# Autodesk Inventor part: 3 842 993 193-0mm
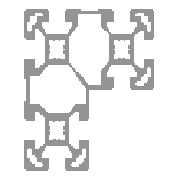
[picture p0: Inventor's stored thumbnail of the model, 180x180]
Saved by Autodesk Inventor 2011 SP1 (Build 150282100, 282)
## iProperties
Category: End -/-
Created: 2011-02
Part Number: 3 842 993 193-0mm
Document SubType Name: Modeling
Designer: SRW
Density: 2.71 g/cm^3
Categories: <MemberInstance><Categories><Category DisplayName="Structural Shapes" InternalName="089c4875-fa83-4c05-b084-43b9cc11f5ed" Mnemonic="GRDR"><CategoryParameter Dis
Stock Number: 3 842 993 193
Description: PROFILE 40x80x80, -/-
Material: Aluminum-6061
Mass: 95.9623 g
Surface Area: 321.468 cm^2
Volume: 35.4105 cm^3
G_L: 25.000 mm
Author: SRW
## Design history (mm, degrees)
node "Blocks"
  sketch "40X80X80"
    geometry: L1 (51.285, 30.766)-(51.552, 30.151); L2 (44.092, 37.611)-(44.706, 37.344); L3 (51.552, 30.151)-(54.492, 30.151); L4 (44.092, 40.551)-(44.092, 37.611); L5 (54.492, 30.151)-(54.492, 33.091); L6 (47.032, 40.551)-(44.092, 40.551); L7 (54.492, 33.091)-(53.878, 33.358); L8 (47.299, 39.937)-(47.032, 40.551); L9 (53.878, 37.344)-(54.492, 37.611); L10 (51.552, 40.551)-(51.285, 39.937); L11 (54.492, 37.611)-(54.492, 40.551); L12 (43.913, 42.851)-(56.085, 42.851); L13 (54.492, 40.551)-(51.552, 40.551); L14 (30.292, 49.351)-(29.292, 49.351); L15 (29.292, 41.151)-(30.792, 41.151); L16 (35.292, 40.351)-(35.292, 45.401); L17 (30.792, 40.351)-(35.292, 40.351); L18 (30.792, 41.151)-(30.792, 40.351); L19 (29.292, 49.351)-(29.292, 41.151); L20 (39.242, 23.887)-(43.206, 27.851); L21 (39.242, 21.351)-(39.242, 23.887); L22 (44.292, 21.351)-(39.242, 21.351); L23 (44.292, 16.783)-(44.292, 21.351); L24 (43.492, 16.783)-(44.292, 16.783); L25 (43.492, 15.283)-(43.492, 16.783); L26 (32.292, 15.283)-(43.492, 15.283); L27 (29.292, 29.551)-(29.292, 18.283); L28 (30.792, 29.551)-(29.292, 29.551); L29 (30.792, 30.351)-(30.792, 29.551); L30 (35.292, 30.351)-(30.792, 30.351); L31 (35.292, 25.301)-(35.292, 30.351); L32 (37.828, 25.301)-(35.292, 25.301); L33 (41.792, 29.265)-(37.828, 25.301); L34 (34.792, 23.601)-(33.792, 23.601); L35 (37.542, 19.851)-(37.542, 20.851); L36 (39.792, 19.851)-(37.542, 19.851); L37 (34.792, 16.851)-(39.792, 16.851); L38 (34.792, 18.101)-(34.792, 16.851); L39 (30.792, 20.851)-(32.042, 20.851); L40 (30.792, 25.851)-(30.792, 20.851); L41 (33.792, 23.601)-(33.792, 25.851); L42 (60.756, 25.301)-(56.792, 29.265); L43 (63.292, 25.301)-(60.756, 25.301); L44 (63.292, 30.351)-(63.292, 25.301); L45 (67.792, 30.351)-(63.292, 30.351); L46 (67.792, 29.551)-(67.792, 30.351); L47 (69.292, 29.551)-(67.792, 29.551); L48 (69.292, 18.283)-(69.292, 29.551); L49 (55.092, 15.283)-(66.292, 15.283); L50 (55.092, 16.783)-(55.092, 15.283); L51 (54.292, 16.783)-(55.092, 16.783); L52 (54.292, 21.351)-(54.292, 16.783); L53 (59.342, 21.351)-(54.292, 21.351); L54 (59.342, 23.887)-(59.342, 21.351); L55 (55.378, 27.851)-(59.342, 23.887); L56 (64.792, 23.601)-(63.792, 23.601); L57 (64.792, 25.851)-(64.792, 23.601); L58 (61.042, 20.851)-(61.042, 19.851); L59 (67.792, 20.851)-(67.792, 25.851); L60 (66.542, 20.851)-(67.792, 20.851); L61 (63.792, 16.851)-(63.792, 18.101); L62 (58.792, 16.851)-(63.792, 16.851); L63 (61.042, 19.851)-(58.792, 19.851); L64 (109.292, 81.151)-(109.292, 92.283)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; A1 r 5 centre (49.292, 35.351) between (53.878, 33.358) and (53.878, 37.344); A2 r 5 centre (49.292, 35.351) between (51.285, 39.937) and (47.299, 39.937); A3 r 3 centre (32.292, 18.283) between (29.292, 18.283) and (32.292, 15.283); A4 r 1.5 centre (32.292, 25.851) between (33.792, 25.851) and (30.792, 25.851); A5 r 1.5 centre (39.792, 18.351) between (39.792, 16.851) and (39.792, 19.851); A6 r 2.75 centre (34.792, 20.851) between (37.542, 20.851) and (34.792, 23.601); A7 r 2.75 centre (34.792, 20.851) between (32.042, 20.851) and (34.792, 18.101); A8 r 3 centre (66.292, 18.283) between (66.292, 15.283) and (69.292, 18.283); A9 r 1.5 centre (66.292, 25.851) between (67.792, 25.851) and (64.792, 25.851); A10 r 1.5 centre (58.792, 18.351) between (58.792, 19.851) and (58.792, 16.851); A11 r 2.75 centre (63.792, 20.851) between (63.792, 23.601) and (61.042, 20.851); A12 r 2.75 centre (63.792, 20.851) between (63.792, 18.101) and (66.542, 20.851); A13 r 3 centre (32.292, 92.283) between (32.292, 95.283) and (29.292, 92.283); A14 r 1.5 centre (32.292, 84.851) between (30.792, 84.851) and (33.792, 84.851); A15 r 2.75 centre (34.792, 89.851) between (34.792, 92.601) and (32.042, 89.851); A16 r 1.5 centre (39.792, 92.351) between (39.792, 90.851) and (39.792, 93.851); A17 r 2.75 centre (34.792, 89.851) between (34.792, 87.101) and (37.542, 89.851); A18 r 1.5 centre (98.792, 92.351) between (98.792, 93.851) and (98.792, 90.851); A19 r 3 centre (106.292, 92.283) between (109.292, 92.283) and (106.292, 95.283); A20 r 5 centre (89.292, 75.351) between (84.706, 77.344) and (84.706, 73.358); A21 r 5 centre (89.292, 75.351) between (91.285, 79.937) and (87.299, 79.937); A22 r 5 centre (89.292, 75.351) between (87.299, 70.766) and (91.285, 70.766); A23 r 5 centre (89.292, 75.351) between (93.877, 73.358) and (93.877, 77.344); A24 r 5 centre (49.292, 35.351) between (47.299, 30.766) and (51.285, 30.766); A25 r 5 centre (49.292, 35.351) between (44.706, 37.344) and (44.706, 33.358); A26 r 1.5 centre (106.292, 84.851) between (104.792, 84.851) and (107.792, 84.851); A27 r 2.75 centre (103.792, 89.851) between (101.042, 89.851) and (103.792, 87.101); A28 r 2.75 centre (103.792, 89.851) between (106.542, 89.851) and (103.792, 92.601); A29 r 5 centre (49.292, 75.351) between (53.878, 73.358) and (53.878, 77.344); A30 r 5 centre (49.292, 75.351) between (51.285, 79.937) and (47.299, 79.937); A31 r 5 centre (49.292, 75.351) between (47.299, 70.766) and (51.285, 70.766); A32 r 5 centre (49.292, 75.351) between (44.706, 77.344) and (44.706, 73.358); A33 r 1.5 centre (106.292, 65.851) between (107.792, 65.851) and (104.792, 65.851); A34 r 2.75 centre (103.792, 60.851) between (103.792, 63.601) and (101.042, 60.851); A35 r 2.75 centre (103.792, 60.851) between (103.792, 58.101) and (106.542, 60.851); A36 r 1.5 centre (98.792, 58.351) between (98.792, 59.851) and (98.792, 56.851); A37 r 3 centre (106.292, 58.351) between (106.292, 55.351) and (109.292, 58.351); 1 further point
    constraints: 478 end point, 74 point on circle, 37 centre point, 1 coincident
node "Start Plane"
node "End Plane"
sketch "Sketch52"
  geometry: L1 (1.993, -44.585)-(2.26, -45.2); L2 (-5.2, -37.74)-(-4.586, -38.007); L3 (2.26, -45.2)-(5.2, -45.2); L4 (-5.2, -34.8)-(-5.2, -37.74); L5 (5.2, -45.2)-(5.2, -42.26); L6 (-2.26, -34.8)-(-5.2, -34.8); L7 (5.2, -42.26)-(4.586, -41.993); L8 (-1.993, -35.414)-(-2.26, -34.8); L9 (4.586, -38.007)-(5.2, -37.74); L10 (2.26, -34.8)-(1.993, -35.414); L11 (5.2, -37.74)-(5.2, -34.8); L12 (-5.379, -32.5)-(6.793, -32.5); L13 (5.2, -34.8)-(2.26, -34.8); L14 (-19, -26)-(-20, -26); L15 (-20, -34.2)-(-18.5, -34.2); L16 (-14, -35)-(-14, -29.95); L17 (-18.5, -35)-(-14, -35); L18 (-18.5, -34.2)-(-18.5, -35); L19 (-20, -26)-(-20, -34.2); L20 (-10.05, -51.464)-(-6.086, -47.5); L21 (-10.05, -54)-(-10.05, -51.464); L22 (-5, -54)-(-10.05, -54); L23 (-5, -58.568)-(-5, -54); L24 (-5.8, -58.568)-(-5, -58.568); L25 (-5.8, -60.068)-(-5.8, -58.568); L26 (-17, -60.068)-(-5.8, -60.068); L27 (-20, -45.8)-(-20, -57.068); L28 (-18.5, -45.8)-(-20, -45.8); L29 (-18.5, -45)-(-18.5, -45.8); L30 (-14, -45)-(-18.5, -45); L31 (-14, -50.05)-(-14, -45); L32 (-11.464, -50.05)-(-14, -50.05); L33 (-7.5, -46.086)-(-11.464, -50.05); L34 (-14.5, -51.75)-(-15.5, -51.75); L35 (-11.75, -55.5)-(-11.75, -54.5); L36 (-9.5, -55.5)-(-11.75, -55.5); L37 (-14.5, -58.5)-(-9.5, -58.5); L38 (-14.5, -57.25)-(-14.5, -58.5); L39 (-18.5, -54.5)-(-17.25, -54.5); L40 (-18.5, -49.5)-(-18.5, -54.5); L41 (-15.5, -51.75)-(-15.5, -49.5); L42 (11.464, -50.05)-(7.5, -46.086); L43 (14, -50.05)-(11.464, -50.05); L44 (14, -45)-(14, -50.05); L45 (18.5, -45)-(14, -45); L46 (18.5, -45.8)-(18.5, -45); L47 (20, -45.8)-(18.5, -45.8); L48 (20, -57.068)-(20, -45.8); L49 (5.8, -60.068)-(17, -60.068); L50 (5.8, -58.568)-(5.8, -60.068); L51 (5, -58.568)-(5.8, -58.568); L52 (5, -54)-(5, -58.568); L53 (10.05, -54)-(5, -54); L54 (10.05, -51.464)-(10.05, -54); L55 (6.086, -47.5)-(10.05, -51.464); L56 (15.5, -51.75)-(14.5, -51.75); L57 (15.5, -49.5)-(15.5, -51.75); L58 (11.75, -54.5)-(11.75, -55.5); L59 (18.5, -54.5)-(18.5, -49.5); L60 (17.25, -54.5)-(18.5, -54.5); L61 (14.5, -58.5)-(14.5, -57.25); L62 (9.5, -58.5)-(14.5, -58.5); L63 (11.75, -55.5)-(9.5, -55.5); L64 (60, 5.8)-(60, 16.932)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; A1 r 5 centre (0, -40) between (4.586, -41.993) and (4.586, -38.007); A2 r 5 centre (0, -40) between (1.993, -35.414) and (-1.993, -35.414); A3 r 3 centre (-17, -57.068) between (-20, -57.068) and (-17, -60.068); A4 r 1.5 centre (-17, -49.5) between (-15.5, -49.5) and (-18.5, -49.5); A5 r 1.5 centre (-9.5, -57) between (-9.5, -58.5) and (-9.5, -55.5); A6 r 2.75 centre (-14.5, -54.5) between (-11.75, -54.5) and (-14.5, -51.75); A7 r 2.75 centre (-14.5, -54.5) between (-17.25, -54.5) and (-14.5, -57.25); A8 r 3 centre (17, -57.068) between (17, -60.068) and (20, -57.068); A9 r 1.5 centre (17, -49.5) between (18.5, -49.5) and (15.5, -49.5); A10 r 1.5 centre (9.5, -57) between (9.5, -55.5) and (9.5, -58.5); A11 r 2.75 centre (14.5, -54.5) between (14.5, -51.75) and (11.75, -54.5); A12 r 2.75 centre (14.5, -54.5) between (14.5, -57.25) and (17.25, -54.5); A13 r 3 centre (-17, 16.932) between (-17, 19.932) and (-20, 16.932); A14 r 1.5 centre (-17, 9.5) between (-18.5, 9.5) and (-15.5, 9.5); A15 r 2.75 centre (-14.5, 14.5) between (-14.5, 17.25) and (-17.25, 14.5); A16 r 1.5 centre (-9.5, 17) between (-9.5, 15.5) and (-9.5, 18.5); A17 r 2.75 centre (-14.5, 14.5) between (-14.5, 11.75) and (-11.75, 14.5); A18 r 1.5 centre (49.5, 17) between (49.5, 18.5) and (49.5, 15.5); A19 r 3 centre (57, 16.932) between (60, 16.932) and (57, 19.932); A20 r 5 centre (40, 0) between (35.414, 1.993) and (35.414, -1.993); A21 r 5 centre (40, 0) between (41.993, 4.586) and (38.007, 4.586); A22 r 5 centre (40, 0) between (38.007, -4.586) and (41.993, -4.586); A23 r 5 centre (40, 0) between (44.585, -1.993) and (44.585, 1.993); A24 r 5 centre (0, -40) between (-1.993, -44.585) and (1.993, -44.585); A25 r 5 centre (0, -40) between (-4.586, -38.007) and (-4.586, -41.993); A26 r 1.5 centre (57, 9.5) between (55.5, 9.5) and (58.5, 9.5); A27 r 2.75 centre (54.5, 14.5) between (51.75, 14.5) and (54.5, 11.75); A28 r 2.75 centre (54.5, 14.5) between (57.25, 14.5) and (54.5, 17.25); A29 r 5 centre (0, 0) between (4.586, -1.993) and (4.586, 1.993); A30 r 5 centre (0, 0) between (1.993, 4.586) and (-1.993, 4.586); A31 r 5 centre (0, 0) between (-1.993, -4.586) and (1.993, -4.586); A32 r 5 centre (0, 0) between (-4.586, 1.993) and (-4.586, -1.993); A33 r 1.5 centre (57, -9.5) between (58.5, -9.5) and (55.5, -9.5); A34 r 2.75 centre (54.5, -14.5) between (54.5, -11.75) and (51.75, -14.5); A35 r 2.75 centre (54.5, -14.5) between (54.5, -17.25) and (57.25, -14.5); A36 r 1.5 centre (49.5, -17) between (49.5, -15.5) and (49.5, -18.5); A37 r 3 centre (57, -17) between (57, -20) and (60, -17)
  constraints: 478 end point, 74 point on circle, 37 centre point, 1 horizontal
extrude "Extrusion13" new body sketch "Sketch52" stored distance "d104" = 10; taper "d105" = 0 deg
node "Driven Length"
  sketch "Sketch55"
    geometry: L1 (0, 0)-(10, 0) reference
    constraints: 2 end point, 1 horizontal
  workplane "Work Plane23"
  sketch "Sketch56"
    geometry: L1 (-36, 0)-(76, 0) reference; L2 (-36, 25)-(76, 25) reference
    dimensions: "d7" = 25 distance between parallel lines of L1 L2 (derived)
sketch "Sketch9"
  geometry: 2 further points
  constraints: 1 vertical alignment
  dimensions: "d88" = 40 distance of point (0, 0) point (0, -40)
hole "M12/-" sketch "Sketch9" at (0, 0), (0, -40) diameter "d17" = 10.106; stored, may be unused: countersink angle "d21" = 90 deg, drill point angle "d23" = 118 deg; dims "d18" = 6, "d19" = 4, "d20" = 2, "d22" = 55
sketch "Sketch10"
  geometry: 2 further points
  constraints: 1 vertical alignment
  dimensions: "d89" = 40 distance of point (0, 0) point (0, -40)
hole "-/M12" sketch "Sketch10" at (0, 0), (0, -40) diameter "d24" = 10.106; stored, may be unused: countersink angle "d28" = 90 deg, drill point angle "d30" = 118 deg; dims "d25" = 6, "d26" = 4, "d27" = 2, "d29" = 55
sketch "Sketch11"
  geometry: L1 (-13.7, 0)-(12.2, 0) reference; C1 r 8.5 at (0, 20); 1 further point
  constraints: 1 centre point, 1 vertical alignment
  dimensions: "d31" = 20 distance from line of C1.centre L1; "d32" = 17 diameter of C1
extrude "D17VS/-" cut sketch "Sketch11" stored distance "d33" = 10; taper "d34" = 0 deg
sketch "Sketch12"
  geometry: L1 (-13.7, 25)-(12.2, 25) reference; C1 r 8.5 at (0, 5); 1 further point
  constraints: 1 centre point, 1 vertical alignment
  dimensions: "d35" = 17 diameter of C1; "d36" = 20 distance from line of L1 C1.centre
extrude "-/D17VS" cut sketch "Sketch12" stored distance "d37" = 10; taper "d38" = 0 deg
sketch "Sketch13"
  geometry: L1 (-12.98, 0)-(7.88, 0) reference; C1 r 4.9 at (0, 20); 1 further point
  constraints: 1 centre point, 1 vertical alignment
  dimensions: "d39" = 9.8 diameter of C1; "d40" = 20 distance from line of C1.centre L1
extrude "D9.8VS/-" cut sketch "Sketch13" stored distance "d41" = 10; taper "d42" = 0 deg
sketch "Sketch14"
  geometry: L1 (-12.98, 25)-(7.88, 25) reference; C1 r 4.9 at (0, 5); 1 further point
  constraints: 1 centre point, 1 vertical alignment
  dimensions: "d43" = 9.8 diameter of C1; "d44" = 20 distance from line of L1 C1.centre
extrude "-/D9.8VS" cut sketch "Sketch14" stored distance "d45" = 10; taper "d46" = 0 deg
sketch "Sketch15"
  geometry: L1 (-54.86, 25)-(14.86, 25) reference; C1 r 4.9 at (0, 5); C2 r 4.9 at (-40, 5); 1 further point
  constraints: 2 centre point, 1 equal radius, 1 horizontal alignment, 1 vertical alignment
  dimensions: "d47" = 9.8 diameter of C1; "d48" = 20 distance from line of L1 C1.centre; "d92" = 40 distance of C1.centre C2.centre
extrude "-/D9.8" cut sketch "Sketch15" stored distance "d49" = 10; taper "d50" = 0 deg
sketch "Sketch26"
  geometry: L1 (-54.86, 0)-(14.86, 0) reference; C1 r 4.9 at (0, 20); C2 r 4.9 at (-40, 20); 1 further point
  constraints: 2 centre point, 1 equal radius, 1 horizontal alignment, 1 vertical alignment
  dimensions: "d62" = 9.8 diameter of C1; "d65" = 20 distance from line of L1 C1.centre; "d93" = 40 distance of C1.centre C2.centre
extrude "D9.8/-" cut sketch "Sketch26" stored distance "d63" = 10; taper "d64" = 0 deg
sketch "Sketch37"
  geometry: L1 (-59.9, 0)-(19.9, 0) reference; L2 (-59.9, 25)-(19.9, 25) reference; C1 r 8.5 at (0, 20); C2 r 8.5 at (-40, 20); 1 further point
  constraints: 2 centre point, 1 equal radius, 1 horizontal alignment, 1 vertical alignment
  dimensions: "d76" = 20 distance from line of C1.centre L1; "d77" = 17 diameter of C1; "d90" = 40 distance of C1.centre C2.centre
extrude "D17/-" cut sketch "Sketch37" stored distance "d78" = 10; taper "d79" = 0 deg
sketch "Sketch38"
  geometry: L1 (-59.9, 25)-(19.9, 25) reference; C1 r 8.5 at (0, 5); C2 r 8.5 at (-40, 5); 1 further point
  constraints: 2 centre point, 1 equal radius, 1 horizontal alignment, 1 vertical alignment
  dimensions: "d80" = 17 diameter of C1; "d81" = 20 distance from line of L1 C1.centre; "d91" = 40 distance of C1.centre C2.centre
extrude "-/D17" cut sketch "Sketch38" stored distance "d82" = 10; taper "d83" = 0 deg
body "Solid1"
other parameters: "Length" = 25, "G_OFFSET_START" = 0 [user parameter; used in 2 equation terms], "G_OFFSET_END" = 0 [user parameter; used in 2 equation terms], "d2" = 0 (computed from G_OFFSET_START), "d3" = 25 (= Length + G_OFFSET_END), "G_L" = 25 (= d7) [user parameter], "Length2" = 25 (= G_OFFSET_START + Length + G_OFFSET_END) [user parameter], "d108" = 90 deg
